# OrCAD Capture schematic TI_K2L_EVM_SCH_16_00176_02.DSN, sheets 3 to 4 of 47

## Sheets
3 PAGE22 : K2L_SOC 1: size C; title: K2L GND AND POWER
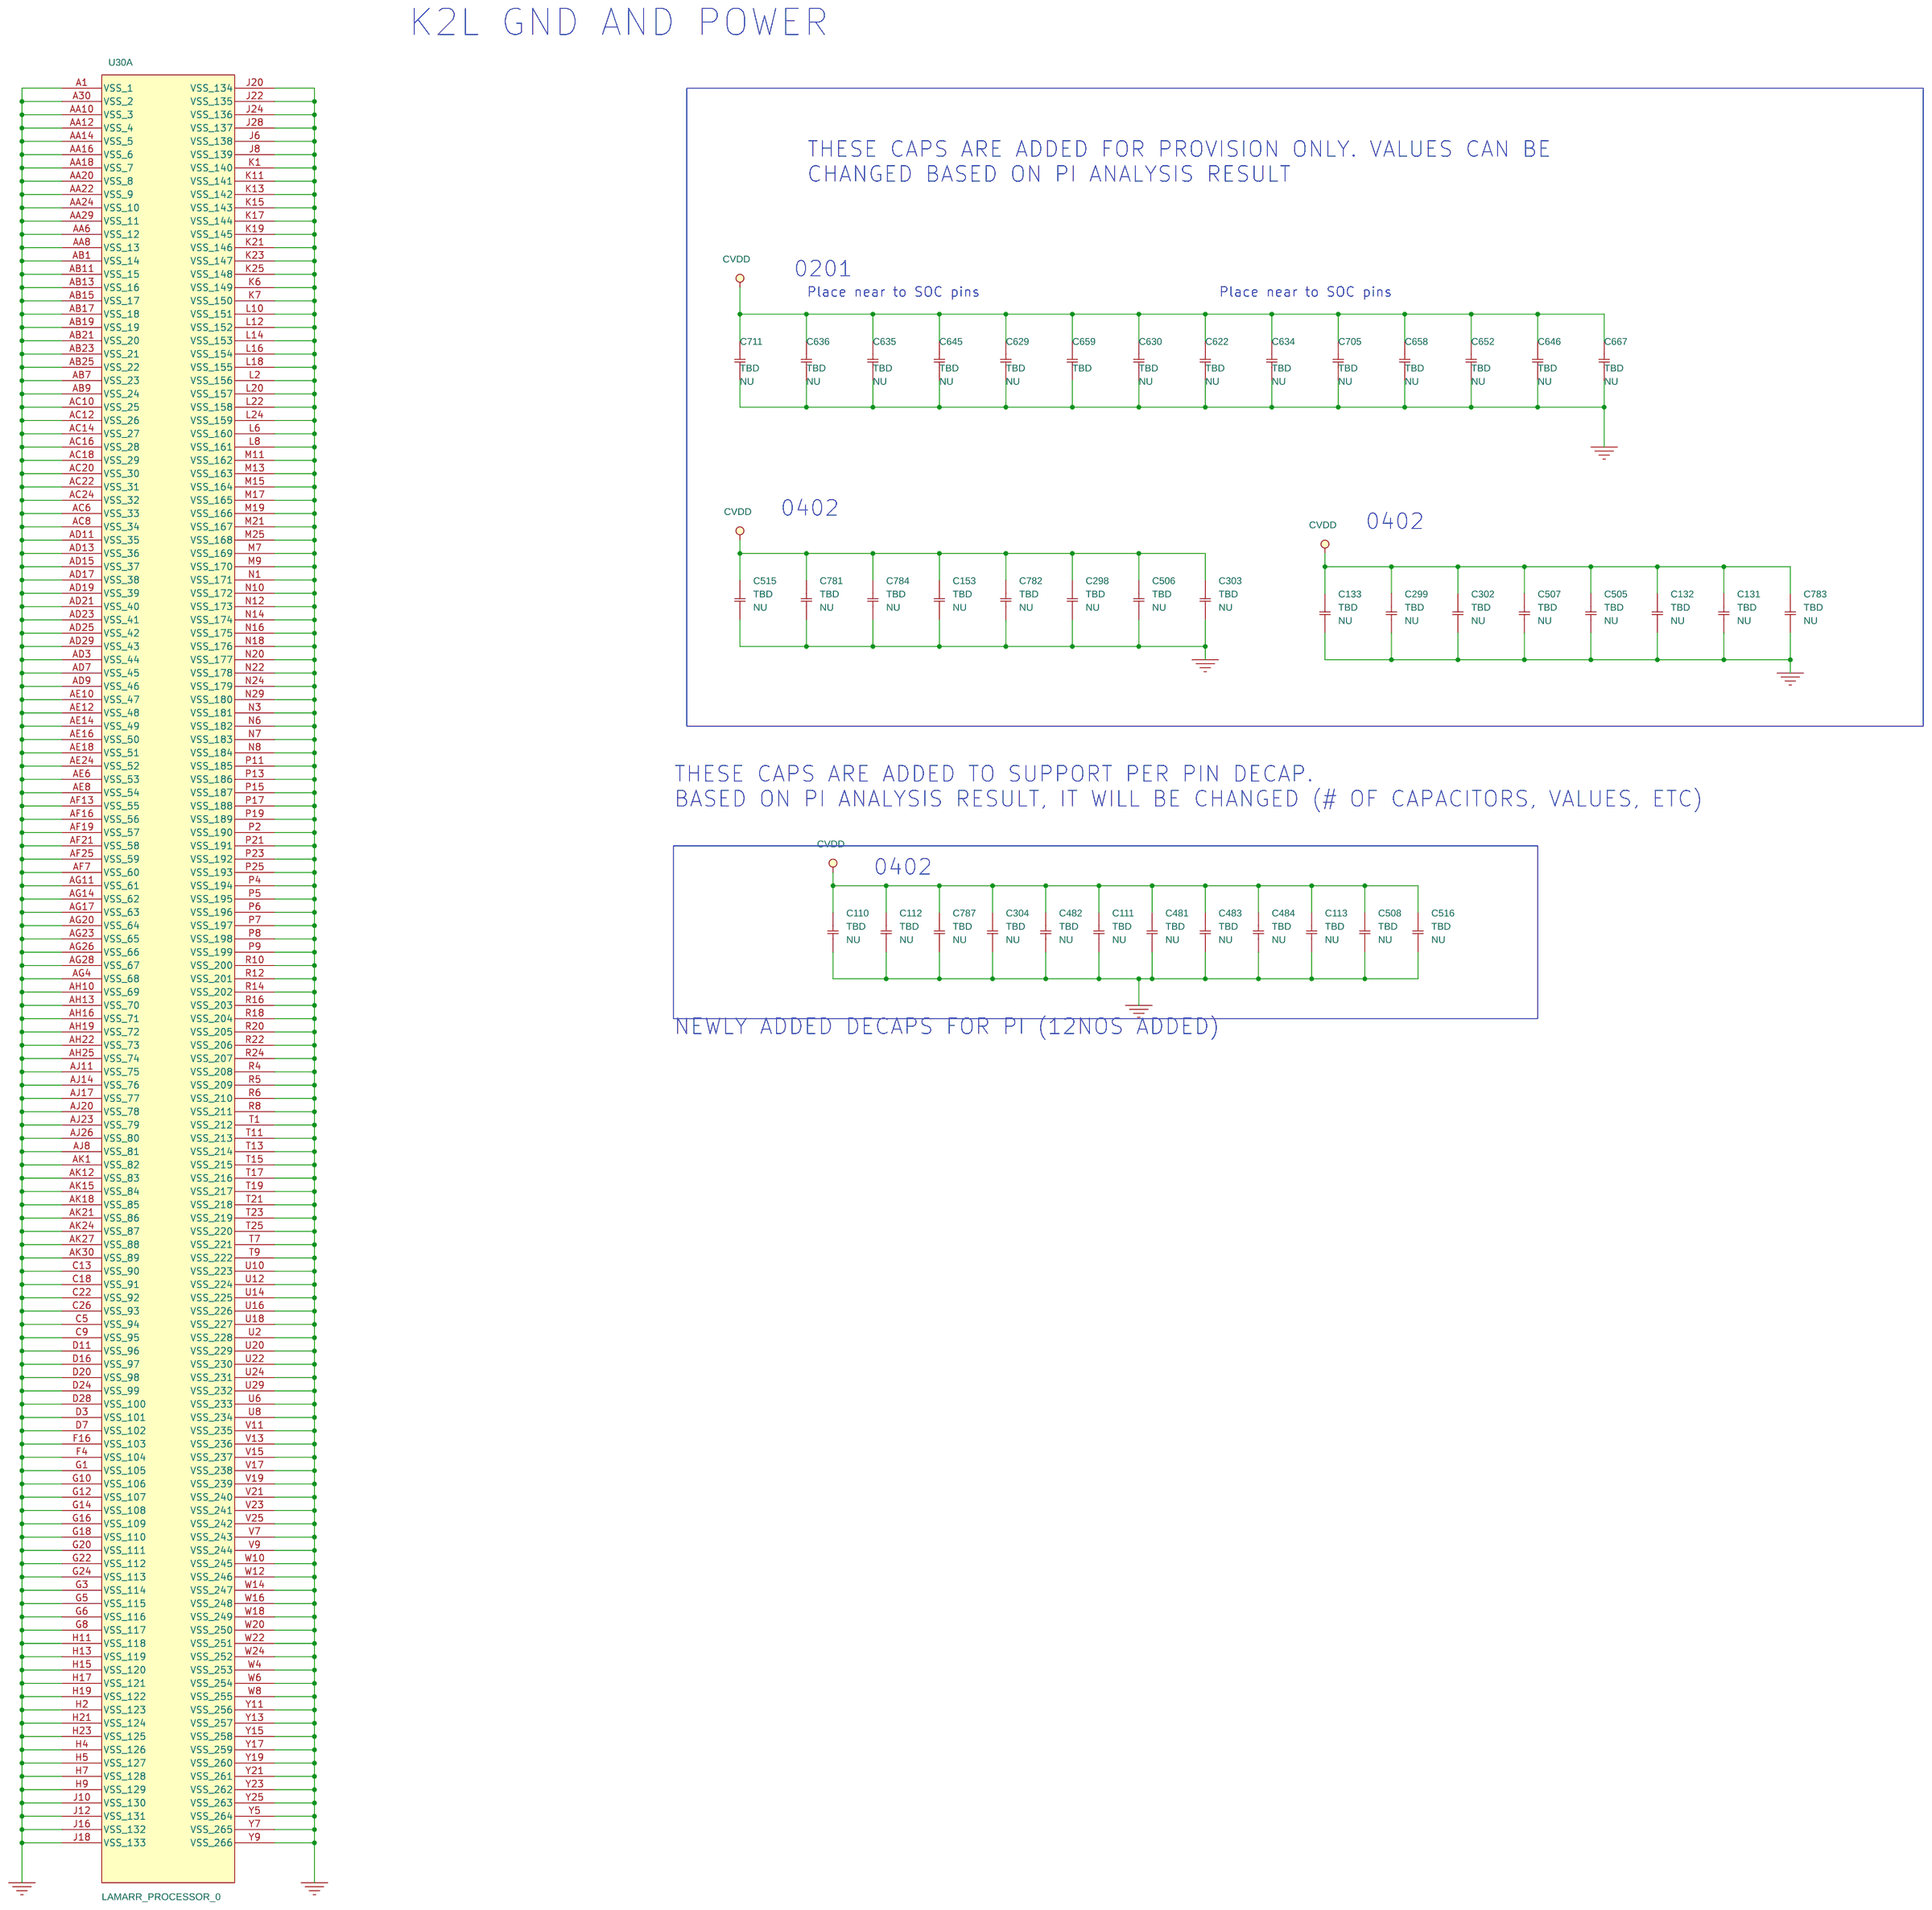
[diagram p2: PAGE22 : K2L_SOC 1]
4 PAGE30 : K2L_LCD: size C; title: LCD, LCD Power, BMC USB for UART, 4pin UART for BMC, BMC
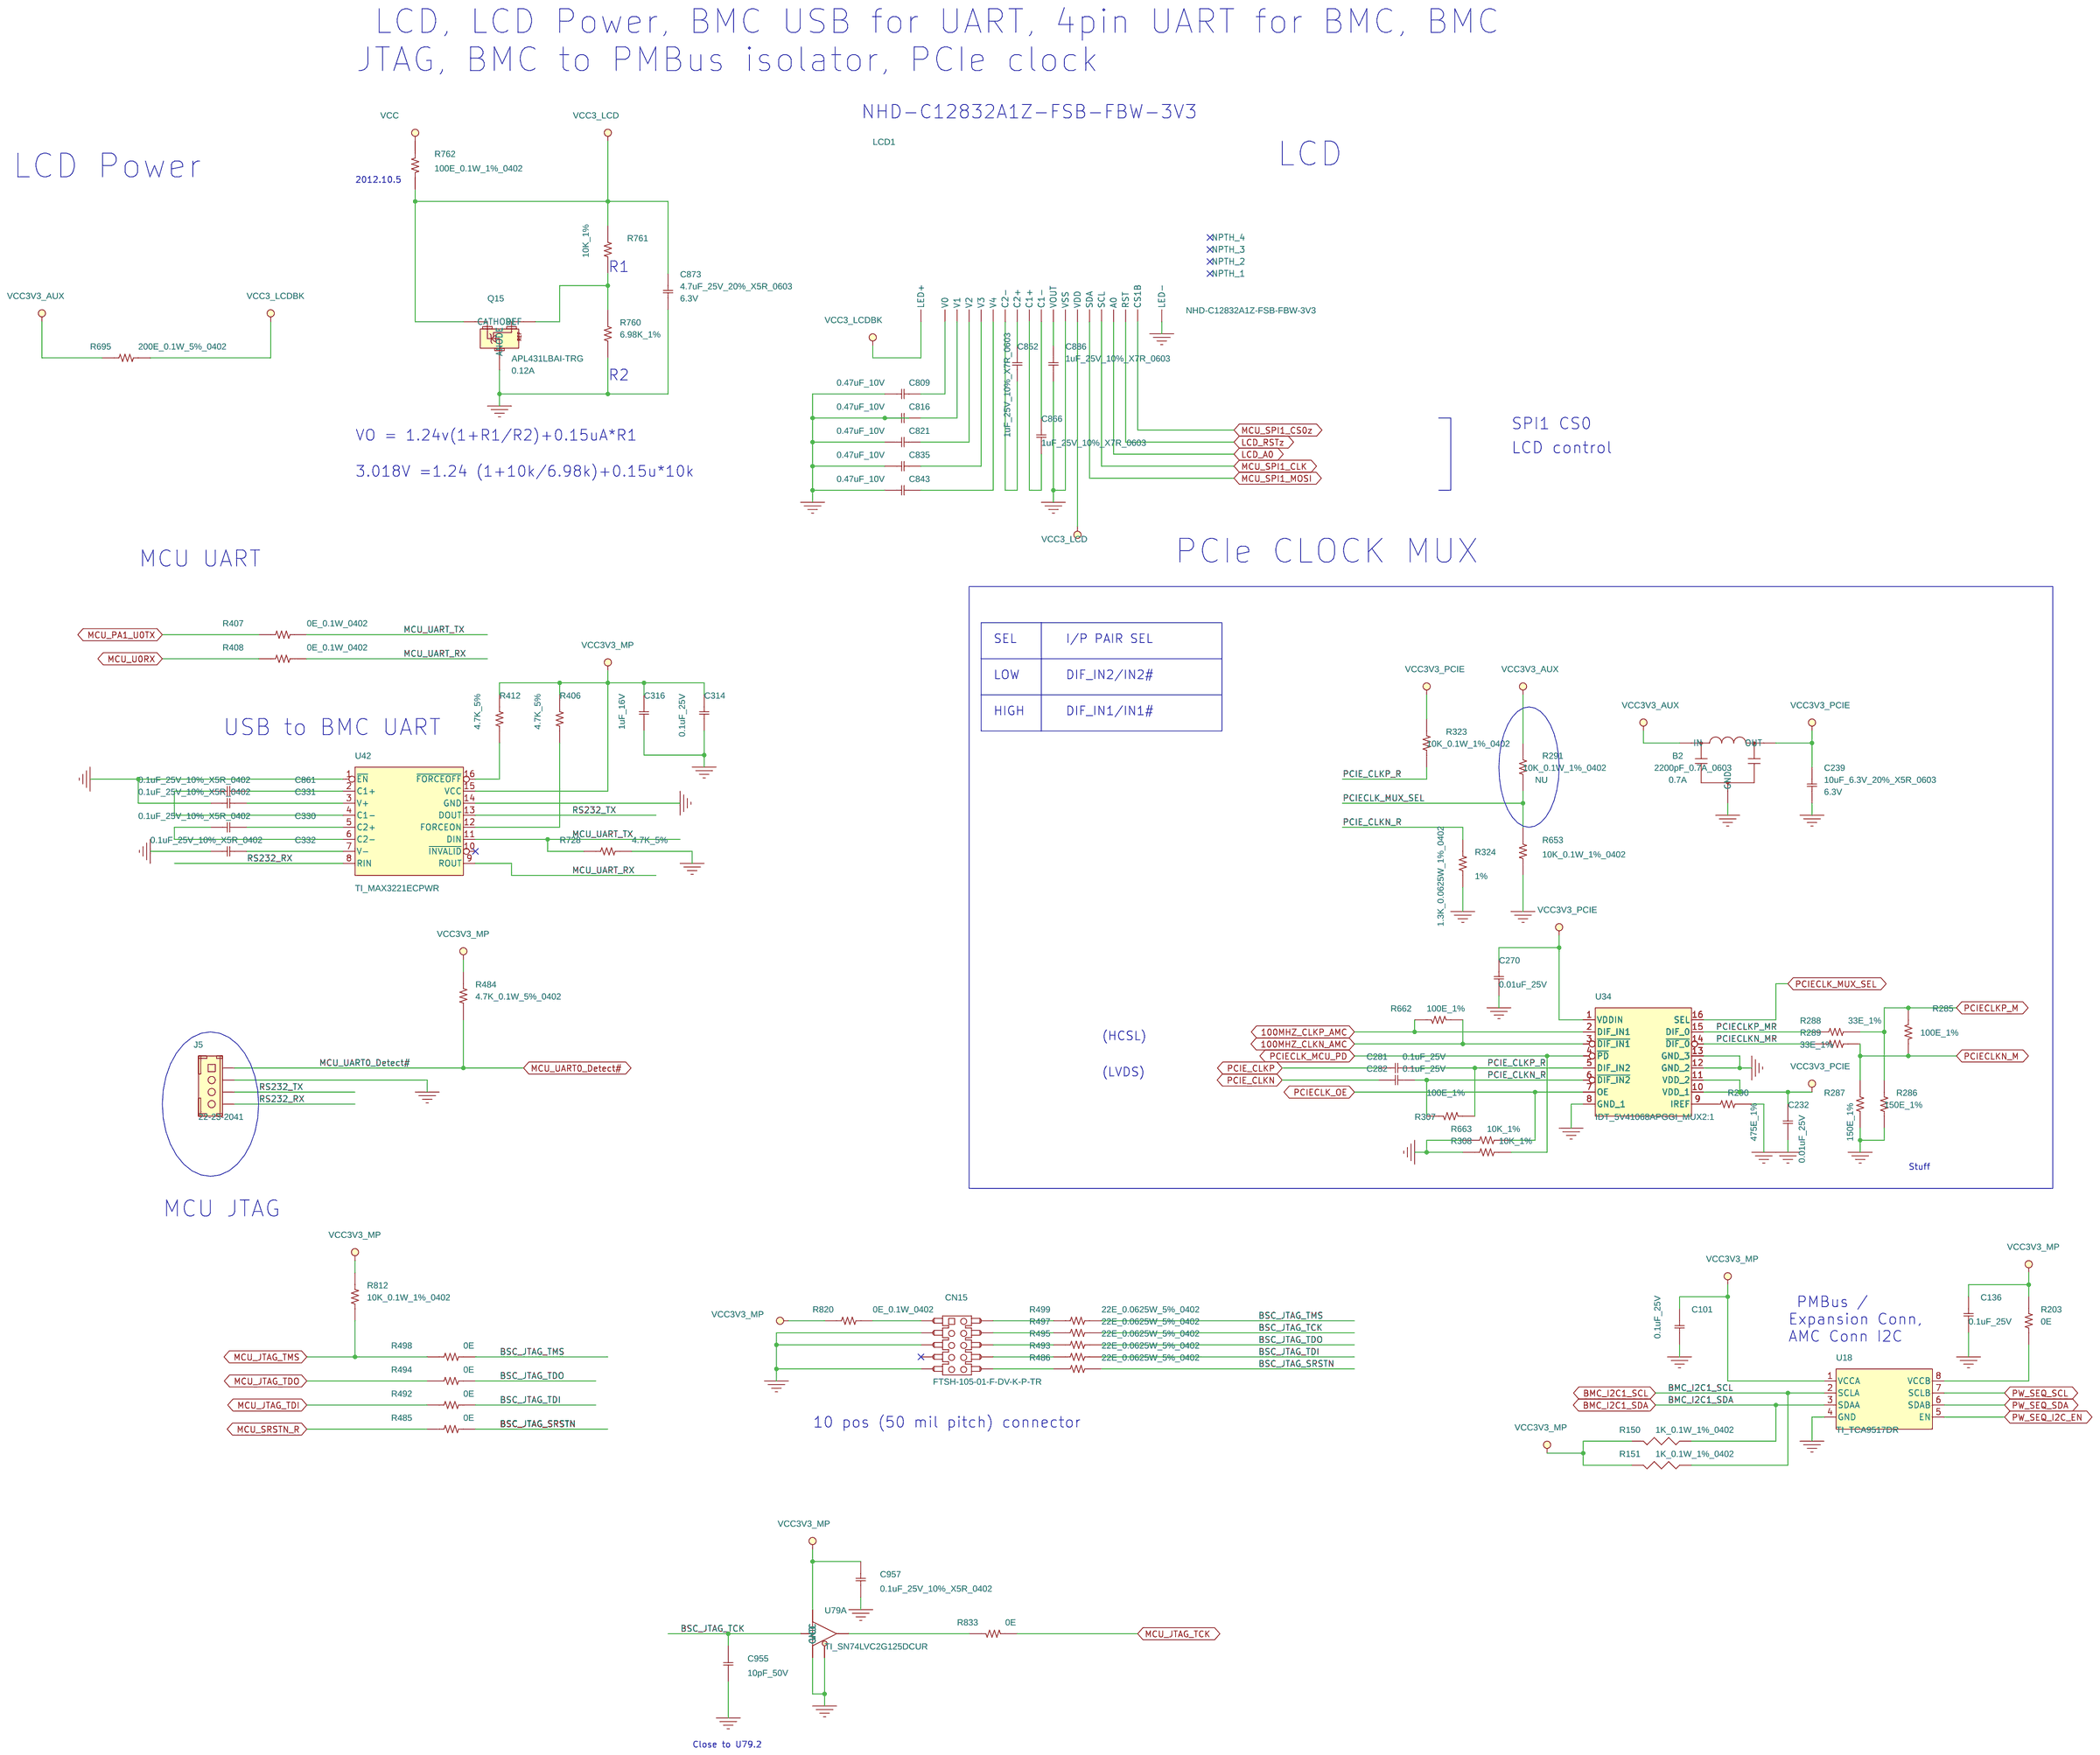
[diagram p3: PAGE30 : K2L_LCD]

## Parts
sheet PAGE22 : K2L_SOC 1
C110  TBD  [C0402]
C111  TBD  [C0402]
C112  TBD  [C0402]
C113  TBD  [C0402]
C131  TBD  [C0402]
C132  TBD  [C0402]
C133  TBD  [C0402]
C153  TBD  [C0402]
C298  TBD  [C0402]
C299  TBD  [C0402]
C302  TBD  [C0402]
C303  TBD  [C0402]
C304  TBD  [C0402]
C481  TBD  [C0402]
C482  TBD  [C0402]
C483  TBD  [C0402]
C484  TBD  [C0402]
C505  TBD  [C0402]
C506  TBD  [C0402]
C507  TBD  [C0402]
C508  TBD  [C0402]
C515  TBD  [C0402]
C516  TBD  [C0402]
C622  TBD  [CC0201_IPC7351_EINF]
C629  TBD  [CC0201_IPC7351_EINF]
C630  TBD  [CC0201_IPC7351_EINF]
C634  TBD  [CC0201_IPC7351_EINF]
C635  TBD  [CC0201_IPC7351_EINF]
C636  TBD  [CC0201_IPC7351_EINF]
C645  TBD  [CC0201_IPC7351_EINF]
C646  TBD  [CC0201_IPC7351_EINF]
C652  TBD  [CC0201_IPC7351_EINF]
C658  TBD  [CC0201_IPC7351_EINF]
C659  TBD  [CC0201_IPC7351_EINF]
C667  TBD  [CC0201_IPC7351_EINF]
C705  TBD  [CC0201_IPC7351_EINF]
C711  TBD  [CC0201_IPC7351_EINF]
C781  TBD  [C0402]
C782  TBD  [C0402]
C783  TBD  [C0402]
C784  TBD  [C0402]
C787  TBD  [C0402]
sheet PAGE24 : K2L_JTAG
U30  LAMARR_PROCESSOR_0  [SKTBGA_Z3566_SS900-RHFB-BGA080]  (sections A,B,C,D,E,F,G,H,I,J,K,L,M,N,O,P,Q,R,S,T,U)
sheet PAGE30 : K2L_LCD
B2  2200pF_0.7A_0603  [L_3P_70_63X35]
C101  0.1uF_25V  [C0402]
C136  0.1uF_25V  [C0402]
C232  0.01uF_25V  [C0402]
C239  10uF_6.3V_20%_X5R_0603  [C0603]
C270  0.01uF_25V  [C0402]
C281  0.1uF_25V  [C0402]
C282  0.1uF_25V  [C0402]
C314  0.1uF_25V  [C0402]
C316  1uF_16V  [C0402]
C330  0.1uF_25V_10%_X5R_0402  [C0402]
C331  0.1uF_25V_10%_X5R_0402  [C0402]
C332  0.1uF_25V_10%_X5R_0402  [C0402]
C809  0.47uF_10V  [C0402]
C816  0.47uF_10V  [C0402]
C821  0.47uF_10V  [C0402]
C835  0.47uF_10V  [C0402]
C843  0.47uF_10V  [C0402]
C852  1uF_25V_10%_X7R_0603  [C0603]
C861  0.1uF_25V_10%_X5R_0402  [C0402]
C866  1uF_25V_10%_X7R_0603  [C0603]
C873  4.7uF_25V_20%_X5R_0603  [C0603]
C886  1uF_25V_10%_X7R_0603  [C0603]
C955  10pF_50V  [C0402]
C957  0.1uF_25V_10%_X5R_0402  [C0402]
CN15  FTSH-105-01-F-DV-K-P-TR  [HD_5x2P_50_H235]
J5  22-23-2041  [MOL22-23-2041]
LCD1  NHD-C12832A1Z-FSB-FBW-3V3  [LCD_17P_NHD-C12832A1Z]
Q15  APL431LBAI-TRG  [SOT-23]
R150  1K_0.1W_1%_0402  [R0402]
R151  1K_0.1W_1%_0402  [R0402]
R203  0E  [R0402]
R285  100E_1%  [R0402]
R286  150E_1%  [R0402]
R287  150E_1%  [R0402]
R288  33E_1%  [R0402]
R289  33E_1%  [R0402]
R290  475E_1%  [R0402]
R291  10K_0.1W_1%_0402  [R0402]
R307  100E_1%  [R0402]
R308  10K_1%  [R0402]
R323  10K_0.1W_1%_0402  [R0402]
R324  1.3K_0.0625W_1%_0402  [R0402]
R406  4.7K_5%  [R0402]
R407  0E_0.1W_0402  [R0402]
R408  0E_0.1W_0402  [R0402]
R412  4.7K_5%  [R0402]
R484  4.7K_0.1W_5%_0402  [R0402]
R485  0E  [R0402]
R486  22E_0.0625W_5%_0402  [R0402]
R492  0E  [R0402]
R493  22E_0.0625W_5%_0402  [R0402]
R494  0E  [R0402]
R495  22E_0.0625W_5%_0402  [R0402]
R497  22E_0.0625W_5%_0402  [R0402]
R498  0E  [R0402]
R499  22E_0.0625W_5%_0402  [R0402]
R653  10K_0.1W_1%_0402  [R0402]
R662  100E_1%  [R0402]
R663  10K_1%  [R0402]
R695  200E_0.1W_5%_0402  [R0402]
R728  4.7K_5%  [R0402]
R760  6.98K_1%  [R0402]
R761  10K_1%  [R0402]
R762  100E_0.1W_1%_0402  [R0402]
R812  10K_0.1W_1%_0402  [R0402]
R820  0E_0.1W_0402  [R0402]
R833  0E  [R0402]
U18  TI_TCA9517DR  [SOIC_8P_50_193X236]
U34  IDT_5V41068APGGI_MUX2:1  [SOIC_16P_26_197x252]
U42  TI_MAX3221ECPWR  [SOIC_16P_26_197x252]
U79  TI_SN74LVC2G125DCUR  [SOIC_8P_20_79X122]  (section A)

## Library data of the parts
C110-C113 C131-C133 C153 C298 C299 C302-C304 C481-C484 C505-C508 C515 C516 C781-C784 C787 = Cap_Ceramic: MOUNTED: <MOUNTED>; MOUNTING_STATUS: NU; Mounting: NU; Oper. Temp. Range: -55°C ~ 85°C; Package: 0402; ProcessType: SMT; RoHS: Yes; Tolerance: 10%
C622 C629 C630 C634-C636 C645 C646 C652 C658 C667 C705 C711 = Cap_Ceramic: MOUNTING_STATUS: NU; Mounting: NU; Oper. Temp. Range: -55C to 125C; Package: 0201; ProcessType: SMT; RoHS: Yes; Tolerance: 10%
C659 = Cap_Ceramic: Mounting: NU; Mounting_Status: NU; Oper. Temp. Range: -55C to 125C; Package: 0201; ProcessType: SMT; RoHS: Yes; Tolerance: 10%
U30 = LAMARR_PROCESSOR_7: LAMARR-SoC 900BGA 4DSP + 2ARM; Color: Default; Distributor_name: TBD; Distributor_part_number: TBD; EIC Part#: TBD; Location X-Coordinate: 0; Location Y-Coordinate: 0; Manufacture: TI; Manufacture Part Number: TCI6630K2L; Manufacture(English): TI; Manufacture_Part_Number: TCI6630K2L; Manufacturer: TI; Manufacturer_Part_No: TCI6630K2L; Mfg: TI; Mfg Part#: TBD; Mfr_name: TI; Mfr_part_number: LAMARR-SoC; Price @ 1: TBD; Price @ 10K: TBD; Price @ 1K: TBD; Primitive: DEFAULT; SPLIT_INST: TRUE; SWAP_INFO: (S1+S2+S3+S4+S5+S6+S7+S8+S9+S10+S11+S12+S13+S14+S15+S16+S17+S18+S19+S20+S21); Vendor: TBD; Vendor_Part_No: TBD; eI Part#: TBD
B2 = 1212_FILTER_NFW31SP106X1E4L_0: EMI Filter 0.7A SMD 3P NFM18CC222R1C3; AVL_Part: AVL; Characteristic: 0.7A; Distributor_name: DIGIKEY; Distributor_part_number: 490-6965-1-ND; EIC Part#: 04_00026_01; Manufacture: Murata; Manufacture Part Number: NFM18CC222R1C3D; Manufacture(English): Murata; Manufacture_Part_Number: NFM18CC222R1C3D; Manufacturer: Murata; Manufacturer_Part_No: NFM18CC222R1C3D; Mfg: Murata Electronics North America; Mfg Part#: 04_00026_01; Mfr_name: Murata; Mfr_part_number: NFM18CC222R1C3D; Package: 0603; Part_Number: 1212002287; Price @ 1: 0.28000; Price @ 10K: 0.09855; Price @ 1K: 0.11242; ProcessType: SMT; Tolerance: 20%; Vendor: DIGIKEY; Vendor_Part_No: 490-6965-1-ND; eI Part#: 04_00026_01
C101 C136 C314 C330-C332 C861 C957 = 11_C_0: CAP CER 0.1UF 25V 10% X5R 0402; Avalue_Part_Number: E1123510400H; Distributor_name: DIGIKEY; Distributor_part_number: 445-4964-1-ND; EIC Part#: 03_00470_02; MOUNTED: <MOUNTED>; Manufacture: TDK Corporation; Manufacture Part Number: C1005X5R1E104K050BC; Manufacture(English): TDK Corporation; Manufacture_Part_Number: GRM155R71C104KA88D; Manufacturer: TDK Corporation; Manufacturer_Part_No: C1005X5R1E104K050BC; Mfg: Murata Electronics North America; Mfg Part#: 03_00470_02; Mfr_name: TDK Corporation; Mfr_part_number: C1005X5R1E104K050BC; Package: 0402; Price @ 1: 0.10000; Price @ 1K: 0.00420; ProcessType: SMT; Tolerance: 10%; Vendor: DIGIKEY; Vendor Part#: 445-4964-1-ND; Vendor_Part_No: 445-4964-1-ND; eI Part#: 03_00470_02
C232 C270 = 11_C_0: CAP CER 10000PF 25V 10% X7R 0402; Advansus_Part_Number: 11G232110312030; Characteristic: 16V; Distributor_name: DIGIKEY; Distributor_part_number: 445-1260-1-ND; EIC Part#: 03_00029_04; GROUP: CPU1; Manufacture: TDK Corporation; Manufacture Part Number: C1005X7R1E103K; Manufacture(English): TDK Corporation; Manufacture_Part_Number: C1005X7R1E103K; Manufacturer: TDK Corporation; Manufacturer_Part_No: C1005X7R1E103K; Mfg: TDK Corporation; Mfg Part#: 03_00029_04; Mfr_name: TDK Corporation; Mfr_part_number: C1005X7R1E103K; Package: 0402; Part_Number: 1121610790; Price @ 1: 0.10000; Price @ 10K: 0.00420; Price @ 1K: 0.00600; ProcessType: SMT; ROOM: CPU1; Tolerance: 10%; Vendor: DIGIKEY; Vendor_Part_No: 445-1260-1-ND; eI Part#: 03_00029_04
C239 = 11_C_0: CAP CER 10UF 6.3V 20% X5R 0603; Avalue_Part_Number: E1121610610H; Characteristic: 6.3V; Distributor_name: DIGIKEY; Distributor_part_number: 587-3383-1-ND; EIC Part#: 03_00605_01; Manufacture: Taiyo Yuden; Manufacture Part Number: JMK107ABJ106MAHT; Manufacture(English): Taiyo Yuden; Manufacture_Part_Number: JMK107ABJ106MAHT; Manufacturer: Taiyo Yuden; Manufacturer_Part_No: JMK107ABJ106MAHT; Mfg: Taiyo Yuden; Mfg Part#: JMK107ABJ106MAHT; Mfr_name: Taiyo Yuden; Mfr_part_number: JMK107ABJ106MAHT; Package: 0603; Part_Number: 1100004184; Price @ 1: 0.32000; Price @ 10K: 0.06105; Price @ 1K: 0.07755; ProcessType: SMT; Tolerance: 20%; Vendor: DIGIKEY; Vendor Part#: 587-3383-1-ND; Vendor_Part_No: 587-3383-1-ND; eI Part#: 03_00605_01
C281 C282 = 11_C_0: CAP CER 0.1UF 25V 10% X5R 0402; Distributor_name: DIGIKEY; Distributor_part_number: 445-4964-1-ND; EIC Part#: 03_00470_02; Manufacture: TDK Corporation; Manufacture Part Number: C1005X5R1E104K050BC; Manufacture(English): TDK Corporation; Manufacture_Part_Number: GRM155R71C104KA88D; Manufacturer: TDK Corporation; Manufacturer_Part_No: C1005X5R1E104K050BC; Mfg: Murata Electronics North America; Mfg Part#: 03_00470_02; Mfr_name: TDK Corporation; Mfr_part_number: C1005X5R1E104K050BC; Package: 0402; Price @ 1: 0.10000; Price @ 1K: 0.00420; ProcessType: SMT; Tolerance: 10%; Vendor: DIGIKEY; Vendor Part#: 445-4964-1-ND; Vendor_Part_No: 445-4964-1-ND; eI Part#: 03_00470_02
C316 = 11_C_0: CAP CER 1UF 16V 10% X5R 0402; Characteristic: 6.3V; Distributor_name: DIGIKEY; Distributor_part_number: 445-4978-1-ND; EIC Part#: 03_00355_04; Manufacture: TDK Corporation; Manufacture Part Number: C1005X5R1C105K050BC; Manufacture(English): TDK Corporation; Manufacture_Part_Number: C1005X5R1C105K050BC; Manufacturer: TDK Corporation; Manufacturer_Part_No: C1005X5R1C105K050BC; Mfg: TDK Corporation; Mfg Part#: C1005X5R1C105K050BC; Mfr_name: TDK Corporation; Mfr_part_number: C1005X5R1C105K050BC; Package: 0402; Part_Number: 1100000870; Price @ 1: 0.10000; Price @ 10K: 0.01155; Price @ 1K: 0.01650; ProcessType: SMT; Tolerance: 10%; Vendor: DIGIKEY; Vendor_Part_No: 445-4978-1-ND; eI Part#: 03_00355_04
C809 C816 C821 C835 C843 = 11_C_0: CAP CER 0.47UF 10V 10% X5R 0402; AVL_Part: AVL; Avalue_Part_Number: E1122547400H; Distributor_name: DIGIKEY; Distributor_part_number: 445-4989-1-ND; EIC Part#: 03_00468_02; Manufacture: TDK Corporation; Manufacture Part Number: C1005X5R1A474K050BB; Manufacture(English): TDK Corporation; Manufacture_Part_Number: C1005X5R1A474K050BB; Manufacturer: TDK Corporation; Manufacturer_Part_No: C1005X5R1A474K050BB; Mfg: TDK Corporation; Mfg Part#: 03_00468_02; Mfr_name: TDK Corporation; Mfr_part_number: C1005X5R1A474K050BB; Package: 0402; Part_Number: 1100004125; Price @ 1: 0.12000; Price @ 10K: 0.01470; Price @ 1K: 0.02100; ProcessType: SMT; Tolerance: 10%; Vendor: DIGIKEY; Vendor_Part_No: 445-4989-1-ND; eI Part#: 03_00468_02
C852 C866 C886 = 11_C_0: CAP CER 1UF 25V 10% X5R 0603; Characteristic: 16V; Distributor_name: DIGIKEY; Distributor_part_number: 490-3897-1-ND; EIC Part#: 03_00161_02; Manufacture: Murata; Manufacture Part Number: GRM188R61E105KA12D; Manufacture(English): Murata; Manufacture_Part_Number: GRM188R71E105KA12D; Manufacturer: Murata; Manufacturer_Part_No: GRM188R61E105KA12D; Mfg: Murata; Mfg Part#: 03_00161_02; Mfr_name: Murata; Mfr_part_number: GRM188R61E105KA12D; Package: 0603; Part_Number: 1100000295; Price @ 1: 0.38000; Price @ 10K: 0.07363; Price @ 1K: 0.09353; ProcessType: SMT; Tolerance: 10%; Vendor: DIGIKEY; Vendor_Part_No: 490-3897-1-ND; eI Part#: 03_00161_02
C873 = 11_C_0: CAP CER 4.7UF 25V 20% X5R 0603; Characteristic: 6.3V; Distributor_name: DIGIKEY; Distributor_part_number: 1276-1903-2-ND; EIC Part#: 03_00592_01; Manufacture: Samsung; Manufacture Part Number: CL10A475MA8NQNC; Manufacture(English): Samsung; Manufacture_Part_Number: CL10A475MA8NQNC; Manufacturer: Samsung; Manufacturer_Part_No: CL10A475MA8NQNC; Mfg: Samsung; Mfg Part#: CL10A475MA8NQNC; Mfr_name: Samsung; Mfr_part_number: CL10A475MA8NQNC; Package: 0603; Part_Number: 1100000213; Price @ 1: 0.16000; Price @ 10K: 0.02322; Price @ 1K: 0.02970; ProcessType: SMT; Tolerance: 10%; Vendor: DIGIKEY; Vendor Part#: 1276-1903-2-ND; Vendor_Part_No: 1276-1903-2-ND; eI Part#: 03_00592_01
C955 = 11_C_0: CAP CER 10PF 50V 5% NPO 0402; Advansus_Part_Number: 11G232010004030; Characteristic: 50V; Distributor_name: DIGIKEY; Distributor_part_number: 490-5921-6-ND; EIC Part#: 03_00366_03; Manufacture: Murata; Manufacture Part Number: GRM1555C1H100JA01D; Manufacture(English): Murata; Manufacture_Part_Number: CC0402JRNPO9BN100; Manufacturer: Murata; Manufacturer_Part_No: GRM1555C1H100JA01D; Mfg: Yageo; Mfg Part#: 03_00366_03; Mfr_name: Murata; Mfr_part_number: GRM1555C1H100JA01D; Package: 0402; Part_Number: 1124410091; Price @ 1: 0.10000; Price @ 10K: 0.00227; Price @ 1K: 0.00324; ProcessType: SMT; Tolerance: 5%; Vendor: DIGIKEY; Vendor_Part_No: 490-5921-6-ND; eI Part#: 03_00366_03
CN15 = 1653_HD_5X2P_0: CONN HEADER 10POS DUAL .05 SMD; AVL_Part: AVL; Distributor_name: DIGIKEY; Distributor_part_number: FTSH-105-01-F-DV-K-P-TR-ND; EIC Part#: TBD; Manufacture: Samtec Inc; Manufacture(English): Samtec Inc; Manufacturer: Samtec Inc; Mfg: Samtec Inc; Mfg Part#: TBD; Mfr_name: Samtec Inc; Package: PH5x2P-S1.27; Part_Number: 1653004493; Price @ 1: 2.19000; Price @ 10K: 1.88000; Price @ 1K: 2.00000; ProcessType: SMT; Vendor: DIGIKEY; Vendor_Part_No: FTSH-105-01-F-DV-K-P-TR-ND; eI Part#: TBD
J5 = 12_WF_4P_BOX_D_0: CONN HEADER 4POS .100 VERT TIN; AVL_Part: AVL; Advansus_Part_Number: 12G080104049; Distributor_name: DIGIKEY; Distributor_part_number: WM4202-ND; EIC Part#: 09_00060_01; Manufacture: Molex Inc; Manufacture(English): Molex Inc; Manufacturer: Molex Inc; Mfg: Molex Inc; Mfg Part#: 09_00060_01; Mfr_name: Molex Inc; Package: WB4P-2.00; Part_Number: 1655000674-01; Price @ 1: 0.37000; Price @ 10K: 0.16192; Price @ 1K: 0.17710; ProcessType: DIP; Vendor: DIGIKEY; Vendor_Part_No: WM4202-ND; eI Part#: 09_00060_01
LCD1 = 968_LCD_17P_NHD-C12832A1Z_0: LCD COG GRAPH 128X32 BLUE BKLT; AVL_Part: Non-AVL; Distributor_name: DIGIKEY; Distributor_part_number: NHD-C12832A1Z-FSB-FBW-3V3-ND; EIC Part#: 06_00465_01; Manufacture: Newhaven Display Intl; Manufacture(English): Newhaven Display Intl; Manufacturer: Newhaven Display Intl; Mfg: Newhaven Display Intl; Mfg Part#: 06_00465_01; Mfr_name: Newhaven Display Intl; Package: LCD-Module17P; Part_Number: 9680014719; Price @ 1: 11.00000; Price @ 10K: 7.92002; Price @ 1K: 7.92002; ProcessType: Others; Vendor: DIGIKEY; Vendor_Part_No: NHD-C12832A1Z-FSB-FBW-3V3-ND; eI Part#: 06_00465_01
Q15 = 131_REG_SOT-23_APL431LBAI_0: REG APL431LBAI-TRG 0.12A 1.24V SMD SOT-23 3P; AVL_Part: AVL; Advansus_Part_Number: 06GA1310003828; Alternate_Mfr: Semtech; Alternate_Partno: SC431LCSK-1TRT; Characteristic: 0.12A; Distributor_name: Alibaba; Distributor_part_number: TBD; EIC Part#: TBD; Manufacture: TBD; Manufacture(English): TBD; Manufacturer: TBD; Mfg: TBD; Mfg Part#: TBD; Mfr_name: TBD; Part_Number: 1310003828; ProcessType: SMT; Vendor: Alibaba; Vendor_Part_No: TBD; eI Part#: TBD
R150 R151 = DISC_RESISTOR: RES 1.00K OHM 1/10W 1% 0402 SMD; Distributor_name: DIGIKEY; Distributor_part_number: P1.00KLCT-ND; EIC Part#: 02_00045_01; Manufacture: Panasonic - ECG; Manufacture Part Number: ERJ-2RKF1001X; Manufacture(English): Panasonic - ECG; Manufacture_Part_Number: ERJ-2RKF1001X; Manufacturer: Panasonic - ECG; Manufacturer_Part_No: ERJ-2RKF1001X; Mfg Part#: 02_00045_01; Mfr_name: Panasonic - ECG; Mfr_part_number: ERJ-2RKF1001X; Operating Temp (Degree Celsius): -55 to 85; Price @ 1: 0.10000; Price @ 10K: 0.00347; Price @ 1K: 0.00672; RoHS Compliant?: RoHS Compliant; Vendor: DIGIKEY; Vendor_Part_No: P1.00KLCT-ND; eI Part#: 02_00045_01
R203 R820 = 10_R_0: RES 0.0 OHM 1/10W JUMP 0402 SMD; Characteristic: 5%; Distributor_name: DIGIKEY; Distributor_part_number: P0.0JCT-ND; EIC Part#: 02_00019_01; MOUNTED: <MOUNTED>; Manufacture: Panasonic - ECG; Manufacture Part Number: ERJ-2GE0R00X; Manufacture(English): Panasonic - ECG; Manufacture_Part_Number: ERJ-2GE0R00X; Manufacturer: Panasonic - ECG; Manufacturer_Part_No: ERJ-2GE0R00X; Mfg: Panasonic Electronic Components; Mfg Part#: 02_00019_01; Mfr_name: Panasonic - ECG; Mfr_part_number: ERJ-2GE0R00X; Package: 0402; Part_Number: 105A700004; Price @ 1: 0.05000; Price @ 10K: 0.00248; Price @ 1K: 0.00480; ProcessType: SMT; Tolerance: 5%; Vendor: DIGIKEY; Vendor_Part_No: P0.0JCT-ND; eI Part#: 02_00019_01
R285 = 10_R_0: RES 100 OHM 1/10W 1% 0402 SMD; Characteristic: 1%; Distributor_name: DIGIKEY; Distributor_part_number: P100LCT-ND; EIC Part#: 02_00043_02; MOUNTED: <MOUNTED>; Manufacture: Panasonic - ECG; Manufacture Part Number: ERJ-2RKF1000X; Manufacture(English): Panasonic - ECG; Manufacture_Part_Number: ERJ-2RKF1000X; Manufacturer: Panasonic - ECG; Manufacturer_Part_No: ERJ-2RKF1000X; Mfg: Panasonic Electronic Components; Mfg Part#: 02_00043_02; Mfr_name: Panasonic - ECG; Mfr_part_number: ERJ-2RKF1000X; Package: 0402; Part_Number: 105A510004; Price @ 1: 0.10000; Price @ 10K: 0.00347; Price @ 1K: 0.00672; ProcessType: SMT; Tolerance: 1%; Vendor: DIGIKEY; Vendor_Part_No: P100LCT-ND; eI Part#: 02_00019_01
R286 = 10_R_0: RES 150E, 1/10W 1% 0402 SMD; Advansus_Part_Number: 10G212151004011; Characteristic: 5%; Distributor_name: DIGIKEY; Distributor_part_number: P150LCT-ND; EIC Part#: 02_00449_01; Manufacture: Panasonic - ECG; Manufacture Part Number: ERJ-2RKF1500X; Manufacture(English): Panasonic - ECG; Manufacture_Part_Number: ERJ-2RKF1500X; Manufacturer: Panasonic - ECG; Manufacturer_Part_No: ERJ-2RKF1500X; Mfg: Panasonic Electronic Components; Mfg Part#: 02_00449_01; Mfr_name: Panasonic - ECG; Mfr_part_number: ERJ-2RKF1500X; Package: 0402; Part_Number: 105A715004-02; Price @ 1: 0.10000; Price @ 10K: 0.00347; Price @ 1K: 0.00672; ProcessType: SMT; Tolerance: 5%; Vendor: DIGIKEY; Vendor_Part_No: P150LCT-ND; eI Part#: 02_00233_01
R287 = 10_R_0: RES 150E, 1/10W 1% 0402 SMD; Advansus_Part_Number: 10G212151004011; Characteristic: 5%; Distributor_name: DIGIKEY; Distributor_part_number: P150LCT-ND; EIC Part#: 02_00449_01; Manufacture: Panasonic - ECG; Manufacture Part Number: ERJ-2RKF1500X; Manufacture(English): Panasonic - ECG; Manufacture_Part_Number: ERJ-2RKF1500X; Manufacturer: Panasonic - ECG; Manufacturer_Part_No: ERJ-2RKF1500X; Mfg: Panasonic Electronic Components; Mfg Part#: 02_00449_01; Mfr_name: Panasonic - ECG; Mfr_part_number: ERJ-2RKF1500X; Package: 0402; Part_Number: 105A715004-02; Price @ 1: 0.10000; Price @ 10K: 0.00347; Price @ 1K: 0.00672; ProcessType: SMT; Tolerance: 5%; Vendor: DIGIKEY; Vendor_Part_No: P150LCT-ND; eI Part#: 02_00045_01
R288 = 10_R_0: RES 33 OHM 1/10W 1% 0402 SMD; Advansus_Part_Number: 10G212330004010; Characteristic: 5%; Distributor_name: DIGIKEY; Distributor_part_number: P33.0LCT-ND; EIC Part#: 02_00018_05; Manufacture: Panasonic - ECG; Manufacture Part Number: ERJ-2RKF33R0X; Manufacture(English): Panasonic - ECG; Manufacture_Part_Number: ERJ-2RKF33R0X; Manufacturer: Panasonic - ECG; Manufacturer_Part_No: ERJ-2RKF33R0X; Mfg: Panasonic Electronic Components; Mfg Part#: 02_00018_05; Mfr_name: Panasonic - ECG; Mfr_part_number: ERJ-2RKF33R0X; Package: 0402; Part_Number: 105A733064-02; Price @ 1: 0.10000; Price @ 10K: 0.00347; Price @ 1K: 0.00672; ProcessType: SMT; Tolerance: 5%; Vendor: DIGIKEY; Vendor_Part_No: P33.0LCT-ND; eI Part#: 02_00233_01
R289 = 10_R_0: RES 33 OHM 1/10W 1% 0402 SMD; Advansus_Part_Number: 10G212330004010; Characteristic: 5%; Distributor_name: DIGIKEY; Distributor_part_number: P33.0LCT-ND; EIC Part#: 02_00018_05; Manufacture: Panasonic - ECG; Manufacture Part Number: ERJ-2RKF33R0X; Manufacture(English): Panasonic - ECG; Manufacture_Part_Number: ERJ-2RKF33R0X; Manufacturer: Panasonic - ECG; Manufacturer_Part_No: ERJ-2RKF33R0X; Mfg: Panasonic Electronic Components; Mfg Part#: 02_00018_05; Mfr_name: Panasonic - ECG; Mfr_part_number: ERJ-2RKF33R0X; Package: 0402; Part_Number: 105A733064-02; Price @ 1: 0.10000; Price @ 10K: 0.00347; Price @ 1K: 0.00672; ProcessType: SMT; Tolerance: 5%; Vendor: DIGIKEY; Vendor_Part_No: P33.0LCT-ND; eI Part#: 02_00045_01
R290 = 10_R_0: RES 475 OHM 1/10W 1% 0402 SMD; AVL_Part: AVL; Advansus_Part_Number: 10G212475014030; Avalue_Part_Number: E1050547500H; Characteristic: 1%; Distributor_name: DIGIKEY; Distributor_part_number: P475LCT-ND; EIC Part#: 02_00690_01; Manufacture: Panasonic - ECG; Manufacture Part Number: ERJ-2RKF4750X; Manufacture(English): Panasonic - ECG; Manufacture_Part_Number: ERJ-2RKF4750X; Manufacturer: Panasonic - ECG; Manufacturer_Part_No: ERJ-2RKF4750X; Mfg: Panasonic Electronic Components; Mfg Part#: 02_00690_01; Mfr_name: Panasonic - ECG; Mfr_part_number: ERJ-2RKF4750X; Package: 0402; Part_Number: 105A54750A-03; Price @ 1: 0.10000; Price @ 10K: 0.00347; Price @ 1K: 0.00672; ProcessType: SMT; Tolerance: 1%; Vendor: DIGIKEY; Vendor_Part_No: P475LCT-ND; eI Part#: 02_00045_01
R291 = 10_R_0: RES 10K OHM 1/10W 1% 0402 SMD; Characteristic: 1%; Distributor_name: DIGIKEY; Distributor_part_number: P10.0KLCT-ND; EIC Part#: 02_00027_01; Manufacture: Panasonic - ECG; Manufacture Part Number: ERJ-2RKF1002X; Manufacture(English): Panasonic - ECG; Manufacture_Part_Number: ERJ-2RKF1002X; Manufacturer: Panasonic - ECG; Manufacturer_Part_No: ERJ-2RKF1002X; Mfg: PANASONIC ELECTRONIC COMPONENTS (VA); Mfg Part#: 02_00027_01; Mfr_name: Panasonic - ECG; Mfr_part_number: ERJ-2RKF1002X; Mounting: NU; Mounting Status: NU; Mounting_Status: NU; Package: 0402; Part_Number: 105A50103A; Price @ 1: 0.10000; Price @ 10K: 0.00347; Price @ 1K: 0.00672; ProcessType: SMT; Tolerance: 1%; Vendor: DIGIKEY; Vendor_Part_No: P10.0KLCT-ND; eI Part#: 02_00027_01
R307 = 10_R_0: RES 100 OHM 1/10W 1% 0402 SMD; Characteristic: 1%; Distributor_name: DIGIKEY; Distributor_part_number: P100LCT-ND; EIC Part#: 02_00043_02; MOUNTED: <MOUNTED>; Manufacture: Panasonic - ECG; Manufacture Part Number: ERJ-2RKF1000X; Manufacture(English): Panasonic - ECG; Manufacture_Part_Number: ERJ-2RKF1000X; Manufacturer: Panasonic - ECG; Manufacturer_Part_No: ERJ-2RKF1000X; Mfg: Panasonic Electronic Components; Mfg Part#: 02_00043_02; Mfr_name: Panasonic - ECG; Mfr_part_number: ERJ-2RKF1000X; Package: 0402; Part_Number: 105A510004; Price @ 1: 0.10000; Price @ 10K: 0.00347; Price @ 1K: 0.00672; ProcessType: SMT; Tolerance: 1%; Vendor: DIGIKEY; Vendor_Part_No: P100LCT-ND; eI Part#: 02_00045_01
R308 R323 R653 R663 R761 R812 = 10_R_0: RES 10K OHM 1/10W 1% 0402 SMD; Characteristic: 1%; Distributor_name: DIGIKEY; Distributor_part_number: P10.0KLCT-ND; EIC Part#: 02_00027_01; Manufacture: Panasonic - ECG; Manufacture Part Number: ERJ-2RKF1002X; Manufacture(English): Panasonic - ECG; Manufacture_Part_Number: ERJ-2RKF1002X; Manufacturer: Panasonic - ECG; Manufacturer_Part_No: ERJ-2RKF1002X; Mfg: PANASONIC ELECTRONIC COMPONENTS (VA); Mfg Part#: 02_00027_01; Mfr_name: Panasonic - ECG; Mfr_part_number: ERJ-2RKF1002X; Package: 0402; Part_Number: 105A50103A; Price @ 1: 0.10000; Price @ 10K: 0.00347; Price @ 1K: 0.00672; ProcessType: SMT; Tolerance: 1%; Vendor: DIGIKEY; Vendor_Part_No: P10.0KLCT-ND; eI Part#: 02_00027_01
R324 = 10_R_0: RES 1.30K OHM 1/16W 1% 0402 SMD; Characteristic: 1%; Distributor_name: DIGIKEY; Distributor_part_number: 541-1.30KLCT-ND; EIC Part#: 02_00894_01; Manufacture: Vishay Dale; Manufacture Part Number: CRCW04021K30FKED; Manufacture(English): Vishay Dale; Manufacture_Part_Number: CRCW04021K30FKED; Manufacturer: Vishay Dale; Manufacturer_Part_No: CRCW04021K30FKED; Mfg: Vishay Dale; Mfg Part#: 02_00894_01; Mfr_name: Vishay Dale; Mfr_part_number: CRCW04021K30FKED; Package: 0402; Part_Number: 1000001932; Price @ 1: 0.08300; Price @ 10K: 0.00540; Price @ 1K: 0.01740; ProcessType: SMT; Tolerance: 1%; Vendor: DIGIKEY; Vendor_Part_No: 541-1.30KLCT-ND; eI Part#: 02_00045_01
R406 R412 R484 R728 = 10_R_0: RES 4.7K OHM 1/10W 5% 0402 SMD; Advansus_Part_Number: 10G212472004030; Avalue_Part_Number: E1050704720H; Characteristic: 5%; Distributor_name: DIGIKEY; Distributor_part_number: P4.7KJCT-ND; EIC Part#: 02_00023_01; MOUNTED: <MOUNTED>; Manufacture: Panasonic - ECG; Manufacture Part Number: ERJ-2GEJ472X; Manufacture(English): Panasonic - ECG; Manufacture_Part_Number: ERJ-2GEJ472X; Manufacturer: Panasonic - ECG; Manufacturer_Part_No: ERJ-2GEJ472X; Mfg: Panasonic Electronic Components; Mfg Part#: 02_00266_01; Mfr_name: Panasonic - ECG; Mfr_part_number: ERJ-2GEJ472X; Package: 0402; Part_Number: 105A747014; Price @ 1: 0.10000; Price @ 10K: 0.00347; Price @ 1K: 0.00672; ProcessType: SMT; Tolerance: 5%; Vendor: DIGIKEY; Vendor_Part_No: P4.7KJCT-ND; eI Part#: 02_00023_01
R407 R408 R485 R492 R494 R498 R833 = 10_R_0: RES 0.0 OHM 1/10W JUMP 0402 SMD; Characteristic: 5%; Distributor_name: DIGIKEY; Distributor_part_number: P0.0JCT-ND; EIC Part#: 02_00019_01; Manufacture: Panasonic - ECG; Manufacture Part Number: ERJ-2GE0R00X; Manufacture(English): Panasonic - ECG; Manufacture_Part_Number: ERJ-2GE0R00X; Manufacturer: Panasonic - ECG; Manufacturer_Part_No: ERJ-2GE0R00X; Mfg: Panasonic Electronic Components; Mfg Part#: 02_00019_01; Mfr_name: Panasonic - ECG; Mfr_part_number: ERJ-2GE0R00X; Package: 0402; Part_Number: 105A700004; Price @ 1: 0.05000; Price @ 10K: 0.00248; Price @ 1K: 0.00480; ProcessType: SMT; Tolerance: 5%; Vendor: DIGIKEY; Vendor_Part_No: P0.0JCT-ND; eI Part#: 02_00019_01
R486 R493 R495 R497 R499 = 10_R_0: RES 22 OHM 1/16W 1% 0402 SMD; Advansus_Part_Number: 10G212270004010; Characteristic: 5%; Distributor_name: DIGIKEY; Distributor_part_number: P22JCT-ND; EIC Part#: 02_00233_01; MOUNTED: <MOUNTED>; Manufacture: Panasonic - ECG; Manufacture Part Number: ERJ-2GEJ220X; Manufacture(English): Panasonic - ECG; Manufacture_Part_Number: ERJ-2GEJ220X; Manufacturer: Panasonic - ECG; Manufacturer_Part_No: ERJ-2GEJ220X; Mfg: Panasonic - ECG; Mfg Part#: ERJ-2GEJ220X; Mfr_name: Panasonic - ECG; Mfr_part_number: ERJ-2GEJ220X; Package: 0402; Part_Number: 105A702704-02; Price @ 1: 0.10000; Price @ 10K: 0.00132; Price @ 1K: 0.00233; ProcessType: SMT; Tolerance: 5%; Vendor: DIGIKEY; Vendor Part#: P22JCT-ND; Vendor_Part_No: P22JCT-ND; eI Part#: 02_00233_01
R662 = 10_R_0: RES 100 OHM 1/10W 1% 0402 SMD; Characteristic: 1%; Distributor_name: DIGIKEY; Distributor_part_number: P100LCT-ND; EIC Part#: 02_00043_02; MOUNTED: <MOUNTED>; Manufacture: Panasonic - ECG; Manufacture Part Number: ERJ-2RKF1000X; Manufacture(English): Panasonic - ECG; Manufacture_Part_Number: ERJ-2RKF1000X; Manufacturer: Panasonic - ECG; Manufacturer_Part_No: ERJ-2RKF1000X; Mfg: Panasonic Electronic Components; Mfg Part#: 02_00043_02; Mfr_name: Panasonic - ECG; Mfr_part_number: ERJ-2RKF1000X; Package: 0402; Part_Number: 105A510004; Price @ 1: 0.10000; Price @ 10K: 0.00347; Price @ 1K: 0.00672; ProcessType: SMT; Tolerance: 1%; Vendor: DIGIKEY; Vendor_Part_No: P100LCT-ND; eI Part#: 02_00233_01
R695 = 10_R_0: RES 200 OHM 1/10W 5% 0402 SMD; Characteristic: 1%; Distributor_name: DIGIKEY; Distributor_part_number: P200JCT-ND; EIC Part#: 02_00022_01; Manufacture: Panasonic - ECG; Manufacture Part Number: ERJ-2GEJ201X; Manufacture(English): Panasonic - ECG; Manufacture_Part_Number: ERJ-2GEJ201X; Manufacturer: Panasonic - ECG; Manufacturer_Part_No: ERJ-2GEJ201X; Mfg: Panasonic Electronic Components; Mfg Part#: 02_00022_01; Mfr_name: Panasonic - ECG; Mfr_part_number: ERJ-2GEJ201X; Package: 0402; Part_Number: 1000000859-02; Price @ 1: 0.10000; Price @ 10K: 0.00248; Price @ 1K: 0.00480; ProcessType: SMT; RoHS: Yes; Tolerance: 5%; Vendor: DIGIKEY; Vendor Part#: P200JTR-ND; Vendor_Part_No: P200JCT-ND; eI Part#: 02_00266_01
R760 = 10_R_0: RES 6.98K OHM 1/16W 1% 0402 SMD; Characteristic: 1%; Distributor_name: DIGIKEY; Distributor_part_number: P6.98KLCT-ND; EIC Part#: 02_00481_01; Manufacture: Panasonic - ECG; Manufacture Part Number: ERJ-2RKF6981X; Manufacture(English): Panasonic - ECG; Manufacture_Part_Number: ERJ-2RKF6981X; Manufacturer: Panasonic - ECG; Manufacturer_Part_No: ERJ-2RKF6981X; Mfg: Panasonic Electronic Components; Mfg Part#: 02_00481_01; Mfr_name: Panasonic - ECG; Mfr_part_number: ERJ-2RKF6981X; Package: 0402; Part_Number: 1000001951-01; Price @ 1: 0.10000; Price @ 10K: 0.00347; Price @ 1K: 0.00672; ProcessType: SMT; Tolerance: 1%; Vendor: DIGIKEY; Vendor_Part_No: P6.98KLCT-ND; eI Part#: 02_00356_01
R762 = 10_R_0: RES 100 OHM 1/10W 1% 0402 SMD; Characteristic: 1%; Distributor_name: DIGIKEY; Distributor_part_number: P100LCT-ND; EIC Part#: 02_00043_02; MOUNTED: <MOUNTED>; Manufacture: Panasonic - ECG; Manufacture Part Number: ERJ-2RKF1000X; Manufacture(English): Panasonic - ECG; Manufacture_Part_Number: ERJ-2RKF1000X; Manufacturer: Panasonic - ECG; Manufacturer_Part_No: ERJ-2RKF1000X; Mfg: Panasonic Electronic Components; Mfg Part#: 02_00043_02; Mfr_name: Panasonic - ECG; Mfr_part_number: ERJ-2RKF1000X; Package: 0402; Part_Number: 105A510004; Price @ 1: 0.10000; Price @ 10K: 0.00347; Price @ 1K: 0.00672; ProcessType: SMT; Tolerance: 1%; Vendor: DIGIKEY; Vendor_Part_No: P100LCT-ND; eI Part#: 02_00348_01
U18 = 141_TI_PCA9517DR_0: IC LVL-TRANSL I2C BUS REP 8-SOIC; AVL_Part: AVL; Alternate_Mfr: TI; Alternate_Partno: TCA9517DR; Distributor_name: DIGIKEY; Distributor_part_number: 296-23734-1-ND; EIC Part#: TBD; Manufacture: TI; Manufacture Part Number: PCA9517DR; Manufacture(English): TI; Manufacture_Part_Number: PCA9517DR; Manufacturer: TI; Manufacturer_Part_No: PCA9517DR; Mfg: TI; Mfg Part#: TBD; Mfr_name: TI; Mfr_part_number: PCA9517DR; Package: SOIC8; Part_Number: 1410015122; Price @ 1: 2.94000; Price @ 10K: 1.35660; Price @ 1K: 1.46880; ProcessType: SMT; Vendor: DIGIKEY; Vendor_Part_No: 296-23734-1-ND; eI Part#: 01_01135_01
U34 = 141_IDT_5V41068A_0: IC CLK MUX 2:1 16TSSOP; AVL_Part: AVL; Distributor_name: DIGIKEY; Distributor_part_number: 800-2530-5-ND; EIC Part#: 01_00854_01; Manufacture: IDT; Manufacture Part Number: IDT5V41068APGGI; Manufacture(English): IDT; Manufacture_Part_Number: IDT5V41068APGGI; Manufacturer: IDT; Manufacturer_Part_No: IDT5V41068APGGI; Mfg: IDT; Mfg Part#: 01_00854_01; Mfr_name: IDT; Mfr_part_number: IDT5V41068APGGI; Package: TSSOP16; Part_Number: 1410023125-01; Price @ 1: 5.09000; Price @ 10K: 2.25432; Price @ 1K: 2.54520; ProcessType: SMT; Vendor: DIGIKEY; Vendor_Part_No: 800-2530-5-ND; eI Part#: 01_01135_01
U42 = 141_TI_MAX3221E_0: IC RS232 3V-5.5V DRVR 16-TSSOP; Distributor_name: DIGIKEY; Distributor_part_number: 296-19825-1-ND; EIC Part#: 01_00390_01; Manufacture: TI; Manufacture Part Number: MAX3221ECPWR; Manufacture(English): TI; Manufacture_Part_Number: MAX3221ECPWR; Manufacturer: TI; Manufacturer_Part_No: MAX3221ECPWR; Mfg: TI; Mfg Part#: 01_00390_01; Mfr_name: TI; Mfr_part_number: MAX3221ECPWR; Package: TSSOP16; Part_Number: 1410020965; Price @ 1: 1.75000; Price @ 10K: 0.74250; Price @ 1K: 0.81950; ProcessType: SMT; Vendor: DIGIKEY; Vendor_Part_No: 296-19825-1-ND; eI Part#: TBD
U79 = 14S_SN74LVC2G125DCUR_US-8_1: IC BUS BUFF TRI-ST DL US8; Advansus_Part_Number: 06G004167030; Avalue_Part_Number: E14S5F12500H; Distributor_name: DIGIKEY; Distributor_part_number: 296-13265-1-ND; EIC Part#: 01_00781_02; Manufacture: TI; Manufacture Part Number: SN74LVC2G125DCUR; Manufacture(English): TI; Manufacture_Part_Number: SN74LVC2G125DCUR; Manufacturer: TI; Manufacturer_Part_No: SN74LVC2G125DCUR; Mfg: TI; Mfg Part#: 01_00781_02; Mfr_name: TI; Mfr_part_number: SN74LVC2G125DCUR; Package: US8; Part_Number: 14S5A12550; Price @ 1: 0.70000; Price @ 10K: 0.24650; Price @ 1K: 0.28050; ProcessType: SMT; Vendor: DIGIKEY; Vendor_Part_No: 296-13265-1-ND; eI Part#: 01_01158_01

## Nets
GND: B2.2(GND) C101.1 C110.1 C111.1 C112.1 C113.1 C131.1 C132.1 C133.1 C136.1 C153.1 C232.1 C239.2 C270.1 C298.1 C299.1 C302.1 C303.1 C304.1 C314.1 C316.2 C331.1 C332.1 C481.1 C482.1 C483.1 C484.1 C505.1 C506.1 C507.1 C508.1 C515.1 C516.1 C622.2 C629.2 C630.2 C634.2 C635.2 C636.2 C645.2 C646.2 C652.2 C658.2 C659.2 C667.2 C705.2 C711.2 C781.1 C782.1 C783.1 C784.1 C787.1 C809.2 C816.2 C821.1 C835.2 C843.1 C873.2 C886.2 C955.2 C957.1 CN15.3 CN15.5 CN15.9 J5.2 LCD1.11(VSS) LCD1.K(LED-) Q15.3(ANODE) R286.2 R287.2 R290.2 R308.2 R324.2 R653.2 R663.2 R728.2 R760.2 U18.4(GND) U30.A1(VSS_1) U30.A30(VSS_2) U30.AA6(VSS_12) U30.AA8(VSS_13) U30.AA10(VSS_3) U30.AA12(VSS_4) U30.AA14(VSS_5) U30.AA16(VSS_6) U30.AA18(VSS_7) U30.AA20(VSS_8) U30.AA22(VSS_9) U30.AA24(VSS_10) U30.AA29(VSS_11) U30.AB1(VSS_14) U30.AB7(VSS_23) U30.AB9(VSS_24) U30.AB11(VSS_15) U30.AB13(VSS_16) U30.AB15(VSS_17) U30.AB17(VSS_18) U30.AB19(VSS_19) U30.AB21(VSS_20) U30.AB23(VSS_21) U30.AB25(VSS_22) U30.AC6(VSS_33) U30.AC8(VSS_34) U30.AC10(VSS_25) U30.AC12(VSS_26) U30.AC14(VSS_27) U30.AC16(VSS_28) U30.AC18(VSS_29) U30.AC20(VSS_30) U30.AC22(VSS_31) U30.AC24(VSS_32) U30.AD3(VSS_44) U30.AD7(VSS_45) U30.AD9(VSS_46) U30.AD11(VSS_35) U30.AD13(VSS_36) U30.AD15(VSS_37) U30.AD17(VSS_38) U30.AD19(VSS_39) U30.AD21(VSS_40) U30.AD23(VSS_41) U30.AD25(VSS_42) U30.AD29(VSS_43) U30.AE6(VSS_53) U30.AE8(VSS_54) U30.AE10(VSS_47) U30.AE12(VSS_48) U30.AE14(VSS_49) U30.AE16(VSS_50) U30.AE18(VSS_51) U30.AE24(VSS_52) U30.AF7(VSS_60) U30.AF13(VSS_55) U30.AF16(VSS_56) U30.AF19(VSS_57) U30.AF21(VSS_58) U30.AF25(VSS_59) U30.AG4(VSS_68) U30.AG11(VSS_61) U30.AG14(VSS_62) U30.AG17(VSS_63) U30.AG20(VSS_64) U30.AG23(VSS_65) U30.AG26(VSS_66) U30.AG28(VSS_67) U30.AH10(VSS_69) U30.AH13(VSS_70) U30.AH16(VSS_71) U30.AH19(VSS_72) U30.AH22(VSS_73) U30.AH25(VSS_74) U30.AJ8(VSS_81) U30.AJ11(VSS_75) U30.AJ14(VSS_76) U30.AJ17(VSS_77) U30.AJ20(VSS_78) U30.AJ23(VSS_79) U30.AJ26(VSS_80) U30.AK1(VSS_82) U30.AK12(VSS_83) U30.AK15(VSS_84) U30.AK18(VSS_85) U30.AK21(VSS_86) U30.AK24(VSS_87) U30.AK27(VSS_88) U30.AK30(VSS_89) U30.C5(VSS_94) U30.C9(VSS_95) U30.C13(VSS_90) U30.C18(VSS_91) U30.C22(VSS_92) U30.C26(VSS_93) U30.D3(VSS_101) U30.D7(VSS_102) U30.D11(VSS_96) U30.D16(VSS_97) U30.D20(VSS_98) U30.D24(VSS_99) U30.D28(VSS_100) U30.F4(VSS_104) U30.F16(VSS_103) U30.G1(VSS_105) U30.G3(VSS_114) U30.G5(VSS_115) U30.G6(VSS_116) U30.G8(VSS_117) U30.G10(VSS_106) U30.G12(VSS_107) U30.G14(VSS_108) U30.G16(VSS_109) U30.G18(VSS_110) U30.G20(VSS_111) U30.G22(VSS_112) U30.G24(VSS_113) U30.H2(VSS_123) U30.H4(VSS_126) U30.H5(VSS_127) U30.H7(VSS_128) U30.H9(VSS_129) U30.H11(VSS_118) U30.H13(VSS_119) U30.H15(VSS_120) U30.H17(VSS_121) U30.H19(VSS_122) U30.H21(VSS_124) U30.H23(VSS_125) U30.J6(VSS_138) U30.J8(VSS_139) U30.J10(VSS_130) U30.J12(VSS_131) U30.J16(VSS_132) U30.J18(VSS_133) U30.J20(VSS_134) U30.J22(VSS_135) U30.J24(VSS_136) U30.J28(VSS_137) U30.K1(VSS_140) U30.K6(VSS_149) U30.K7(VSS_150) U30.K11(VSS_141) U30.K13(VSS_142) U30.K15(VSS_143) U30.K17(VSS_144) U30.K19(VSS_145) U30.K21(VSS_146) U30.K23(VSS_147) U30.K25(VSS_148) U30.L2(VSS_156) U30.L6(VSS_160) U30.L8(VSS_161) U30.L10(VSS_151) U30.L12(VSS_152) U30.L14(VSS_153) U30.L16(VSS_154) U30.L18(VSS_155) U30.L20(VSS_157) U30.L22(VSS_158) U30.L24(VSS_159) U30.M7(VSS_169) U30.M9(VSS_170) U30.M11(VSS_162) U30.M13(VSS_163) U30.M15(VSS_164) U30.M17(VSS_165) U30.M19(VSS_166) U30.M21(VSS_167) U30.M25(VSS_168) U30.N1(VSS_171) U30.N3(VSS_181) U30.N6(VSS_182) U30.N7(VSS_183) U30.N8(VSS_184) U30.N10(VSS_172) U30.N12(VSS_173) U30.N14(VSS_174) U30.N16(VSS_175) U30.N18(VSS_176) U30.N20(VSS_177) U30.N22(VSS_178) U30.N24(VSS_179) U30.N29(VSS_180) U30.P2(VSS_190) U30.P4(VSS_194) U30.P5(VSS_195) U30.P6(VSS_196) U30.P7(VSS_197) U30.P8(VSS_198) U30.P9(VSS_199) U30.P11(VSS_185) U30.P13(VSS_186) U30.P15(VSS_187) U30.P17(VSS_188) U30.P19(VSS_189) U30.P21(VSS_191) U30.P23(VSS_192) U30.P25(VSS_193) U30.R4(VSS_208) U30.R5(VSS_209) U30.R6(VSS_210) U30.R8(VSS_211) U30.R10(VSS_200) U30.R12(VSS_201) U30.R14(VSS_202) U30.R16(VSS_203) U30.R18(VSS_204) U30.R20(VSS_205) U30.R22(VSS_206) U30.R24(VSS_207) U30.T1(VSS_212) U30.T7(VSS_221) U30.T9(VSS_222) U30.T11(VSS_213) U30.T13(VSS_214) U30.T15(VSS_215) U30.T17(VSS_216) U30.T19(VSS_217) U30.T21(VSS_218) U30.T23(VSS_219) U30.T25(VSS_220) U30.U2(VSS_228) U30.U6(VSS_233) U30.U8(VSS_234) U30.U10(VSS_223) U30.U12(VSS_224) U30.U14(VSS_225) U30.U16(VSS_226) U30.U18(VSS_227) U30.U20(VSS_229) U30.U22(VSS_230) U30.U24(VSS_231) U30.U29(VSS_232) U30.V7(VSS_243) U30.V9(VSS_244) U30.V11(VSS_235) U30.V13(VSS_236) U30.V15(VSS_237) U30.V17(VSS_238) U30.V19(VSS_239) U30.V21(VSS_240) U30.V23(VSS_241) U30.V25(VSS_242) U30.W4(VSS_253) U30.W6(VSS_254) U30.W8(VSS_255) U30.W10(VSS_245) U30.W12(VSS_246) U30.W14(VSS_247) U30.W16(VSS_248) U30.W18(VSS_249) U30.W20(VSS_250) U30.W22(VSS_251) U30.W24(VSS_252) U30.Y5(VSS_264) U30.Y7(VSS_265) U30.Y9(VSS_266) U30.Y11(VSS_256) U30.Y13(VSS_257) U30.Y15(VSS_258) U30.Y17(VSS_259) U30.Y19(VSS_260) U30.Y21(VSS_261) U30.Y23(VSS_262) U30.Y25(VSS_263) U34.8(GND_1) U34.12(GND_2) U34.13(GND_3) U42.1(~{EN}) U42.14(GND) U79.1 U79.4(GND) ; also on sheet 1 2 5 6 8 10 11 12 13 14 15 16 17 18 19 20 21 22 24 25 26 27 28 29 33 34 35 36 37 40 41 42 43 45 46 47
VCC3_LCD: C873.1 LCD1.12(VDD) Q15.2(CATHODE) R761.1 R762.1
VCC3_LCDBK: LCD1.A(LED+) R695.2
VCC3V3_AUX: B2.1(IN) R291.1 R695.1 ; also on sheet 2 6 8 11 12 13 16 18 19 22 25 26 27 28 29 33 35 37 40 45 47
VCC3V3_MP: C101.2 C136.2 C314.2 C316.1 C957.2 R150.2 R151.2 R203.1 R406.1 R412.1 R484.1 R762.2 R812.2 R820.2 U18.1(VCCA) U42.15(VCC) U79.8(VCC) ; also on sheet 5 18 22 37 41
VCC3V3_PCIE: B2.3(OUT) C232.2 C239.1 C270.2 R323.1 U34.1(VDDIN) U34.10(VDD_1) U34.11(VDD_2)
100MHZ_CLKN_AMC: R662.1 U34.3(~{DIF_IN1}) ; also on sheet 18
100MHZ_CLKP_AMC: R662.2 U34.2(DIF_IN1) ; also on sheet 18
BMC_I2C1_SCL: R151.1 U18.2(SCLA) ; also on sheet 5 40 41 45 47
BMC_I2C1_SDA: R150.1 U18.3(SDAA) ; also on sheet 5 40 41 45 47
BSC_JTAG_SRSTN: R485.1 R486.1
BSC_JTAG_TCK: C955.1 R497.1 U79.2
BSC_JTAG_TDI: R492.1 R493.1
BSC_JTAG_TDO: R494.1 R495.1
BSC_JTAG_TMS: R498.1 R499.1
CVDD: C110.2 C111.2 C112.2 C113.2 C131.2 C132.2 C133.2 C153.2 C298.2 C299.2 C302.2 C303.2 C304.2 C481.2 C482.2 C483.2 C484.2 C505.2 C506.2 C507.2 C508.2 C515.2 C516.2 C622.1 C629.1 C630.1 C634.1 C635.1 C636.1 C645.1 C646.1 C652.1 C658.1 C659.1 C667.1 C705.1 C711.1 C781.2 C782.2 C783.2 C784.2 C787.2 ; also on sheet 35 36 37
LCD_A0: LCD1.15(A0) ; also on sheet 5
LCD_RSTz: LCD1.16(RST) ; also on sheet 5
MCU_JTAG_TCK: R833.2 ; also on sheet 5
MCU_JTAG_TDI: R492.2 ; also on sheet 5
MCU_JTAG_TDO: R494.2 ; also on sheet 5
MCU_JTAG_TMS: R498.2 R812.1 ; also on sheet 5
MCU_PA1_U0TX: R407.2 ; also on sheet 5 8
MCU_SPI1_CLK: LCD1.14(SCL) ; also on sheet 5
MCU_SPI1_CS0z: LCD1.17(CS1B) ; also on sheet 5
MCU_SPI1_MOSI: LCD1.13(SDA) ; also on sheet 5
MCU_SRSTN_R: R485.2 ; also on sheet 5
MCU_U0RX: R408.2 ; also on sheet 5
MCU_UART0_Detect#: J5.1 R484.2 ; also on sheet 5
MCU_UART_RX: R408.1 U42.9(ROUT)
MCU_UART_TX: R407.1 R728.1 U42.11(DIN)
PCIE_CLKN: C282.1 ; also on sheet 13
PCIE_CLKN_R: C282.2 R307.2 R324.1 U34.6(~{DIF_IN2})
PCIE_CLKP: C281.1 ; also on sheet 13
PCIE_CLKP_R: C281.2 R307.1 R323.2 U34.5(DIF_IN2)
PCIECLK_MCU_PD: R308.1 U34.4(~{PD}) ; also on sheet 5
PCIECLK_MUX_SEL: R291.2 R653.1 U34.16(SEL) ; also on sheet 5
PCIECLK_OE: R663.1 U34.7(OE) ; also on sheet 5
PCIECLKN_M: R285.1 R287.1 R289.1 ; also on sheet 16
PCIECLKN_MR: R289.2 U34.14(~{DIF_0})
PCIECLKP_M: R285.2 R286.1 R288.1 ; also on sheet 16
PCIECLKP_MR: R288.2 U34.15(DIF_0)
PW_SEQ_I2C_EN: U18.5(EN) ; also on sheet 5
PW_SEQ_SCL: U18.7(SCLB) ; also on sheet 26 37
PW_SEQ_SDA: U18.6(SDAB) ; also on sheet 26 37
RS232_RX: J5.4 U42.8(RIN)
RS232_TX: J5.3 U42.13(DOUT)
N17873281: C809.1 LCD1.1(V0)
N17873283: C816.1 LCD1.2(V1)
N17873285: C821.2 LCD1.3(V2)
N17873287: C835.1 LCD1.4(V3)
N17873289: C843.2 LCD1.5(V4)
N17873369: C852.1 LCD1.6(C2-)
N17873371: C852.2 LCD1.7(C2+)
N17873379: C866.2 LCD1.8(C1+)
N17873403: C866.1 LCD1.9(C1-)
N17873431: C886.1 LCD1.10(VOUT)
N17873524: Q15.1(REF) R760.1 R761.2
N17874656: R406.2 U42.12(FORCEON)
N17874690: C331.2 U42.3(V+)
N17874692: C330.2 U42.5(C2+)
N17874694: C330.1 U42.6(C2-)
N17874700: C861.2 U42.2(C1+)
N17874702: C861.1 U42.4(C1-)
N17874710: C332.2 U42.7(V-)
N17874714: R412.2 U42.16(~{FORCEOFF})
N17876700: R203.2 U18.8(VCCB)
N17880902: CN15.1 R820.1
N17880960: CN15.2 R499.2
N17880962: CN15.4 R497.2
N17880964: CN15.6 R495.2
N17880966: CN15.8 R493.2
N17880968: CN15.10 R486.2
N17881030: R833.1 U79.6
N23542962: R290.1 U34.9(IREF)

Not connected (* = marked no-connect by the designer): CN15 7*; LCD1 H1(NPTH_1)* H2(NPTH_2)* H3(NPTH_3)* H4(NPTH_4)*; U42 10(~{INVALID})*

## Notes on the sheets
sheet 3
- K2L GND AND POWER
- THESE CAPS ARE ADDED FOR PROVISION ONLY. VALUES CAN BE
  CHANGED BASED ON PI ANALYSIS RESULT
- 0201
- Place near to SOC pins
- Place near to SOC pins
- 0402
- 0402
- THESE CAPS ARE ADDED TO SUPPORT PER PIN DECAP.
  BASED ON PI ANALYSIS RESULT, IT WILL BE CHANGED (# OF CAPACITORS, VALUES, ETC)
- 0402
- NEWLY ADDED DECAPS FOR PI (12NOS ADDED)
sheet 4
- LCD, LCD Power, BMC USB for UART, 4pin UART for BMC, BMC
  JTAG, BMC to PMBus isolator, PCIe clock
- NHD-C12832A1Z-FSB-FBW-3V3
- LCD
- LCD Power
- 2012.10.5
- R1
- R2
- SPI1 CS0
- VO = 1.24v(1+R1/R2)+0.15uA*R1
- LCD control
- 3.018V =1.24 (1+10k/6.98k)+0.15u*10k
- PCIe CLOCK MUX
- MCU UART
- SEL
- I/P PAIR SEL
- LOW
- DIF_IN2/IN2#
- HIGH
- DIF_IN1/IN1#
- USB to BMC UART
- (HCSL)
- (LVDS)
- Stuff
- MCU JTAG
- PMBus /
  Expansion Conn,
  AMC Conn I2C
- 10 pos (50 mil pitch) connector
- Close to U79.2
